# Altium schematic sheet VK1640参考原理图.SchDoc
size A4
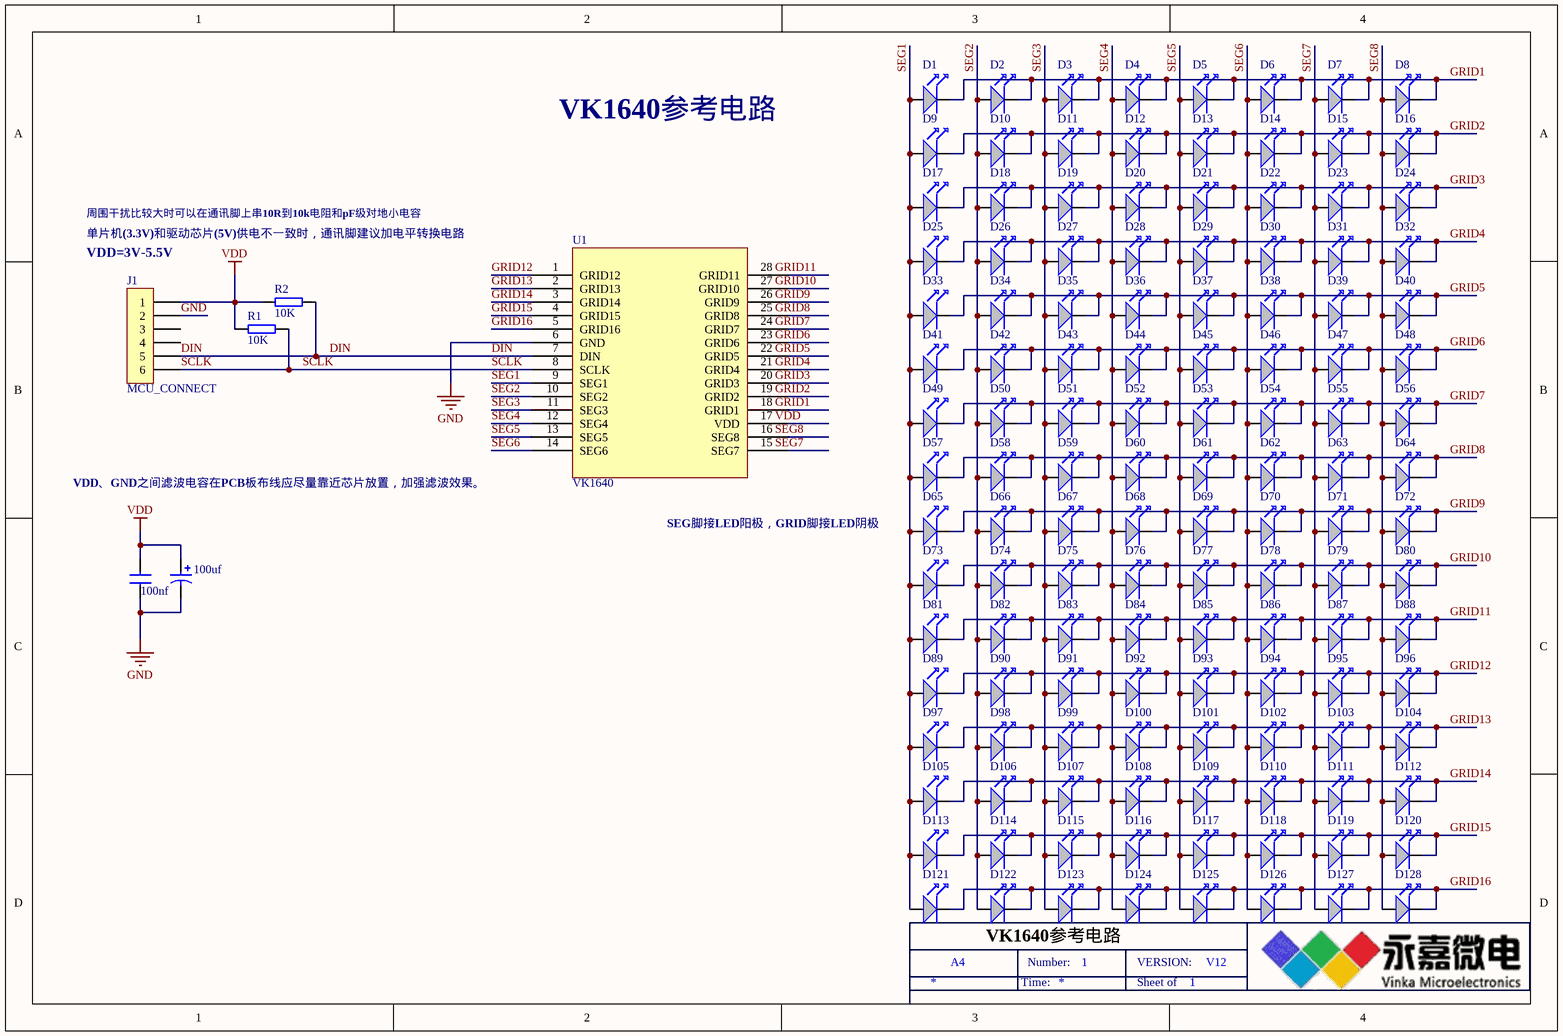
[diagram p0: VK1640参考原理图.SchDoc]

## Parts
100nf  CAP  (value not drawn)
100uf  CAP2  (value not drawn)
D1  (no value)  [1206-LED]
D2  (no value)  [1206-LED]
D3  (no value)  [1206-LED]
D4  (no value)  [1206-LED]
D5  (no value)  [1206-LED]
D6  (no value)  [1206-LED]
D7  (no value)  [1206-LED]
D8  (no value)  [1206-LED]
D9  (no value)  [1206-LED]
D10  (no value)  [1206-LED]
D11  (no value)  [1206-LED]
D12  (no value)  [1206-LED]
D13  (no value)  [1206-LED]
D14  (no value)  [1206-LED]
D15  (no value)  [1206-LED]
D16  (no value)  [1206-LED]
D17  (no value)  [1206-LED]
D18  (no value)  [1206-LED]
D19  (no value)  [1206-LED]
D20  (no value)  [1206-LED]
D21  (no value)  [1206-LED]
D22  (no value)  [1206-LED]
D23  (no value)  [1206-LED]
D24  (no value)  [1206-LED]
D25  (no value)  [1206-LED]
D26  (no value)  [1206-LED]
D27  (no value)  [1206-LED]
D28  (no value)  [1206-LED]
D29  (no value)  [1206-LED]
D30  (no value)  [1206-LED]
D31  (no value)  [1206-LED]
D32  (no value)  [1206-LED]
D33  (no value)  [1206-LED]
D34  (no value)  [1206-LED]
D35  (no value)  [1206-LED]
D36  (no value)  [1206-LED]
D37  (no value)  [1206-LED]
D38  (no value)  [1206-LED]
D39  (no value)  [1206-LED]
D40  (no value)  [1206-LED]
D41  (no value)  [1206-LED]
D42  (no value)  [1206-LED]
D43  (no value)  [1206-LED]
D44  (no value)  [1206-LED]
D45  (no value)  [1206-LED]
D46  (no value)  [1206-LED]
D47  (no value)  [1206-LED]
D48  (no value)  [1206-LED]
D49  (no value)  [1206-LED]
D50  (no value)  [1206-LED]
D51  (no value)  [1206-LED]
D52  (no value)  [1206-LED]
D53  (no value)  [1206-LED]
D54  (no value)  [1206-LED]
D55  (no value)  [1206-LED]
D56  (no value)  [1206-LED]
D57  (no value)  [1206-LED]
D58  (no value)  [1206-LED]
D59  (no value)  [1206-LED]
D60  (no value)  [1206-LED]
D61  (no value)  [1206-LED]
D62  (no value)  [1206-LED]
D63  (no value)  [1206-LED]
D64  (no value)  [1206-LED]
D65  (no value)  [1206-LED]
D66  (no value)  [1206-LED]
D67  (no value)  [1206-LED]
D68  (no value)  [1206-LED]
D69  (no value)  [1206-LED]
D70  (no value)  [1206-LED]
D71  (no value)  [1206-LED]
D72  (no value)  [1206-LED]
D73  (no value)  [1206-LED]
D74  (no value)  [1206-LED]
D75  (no value)  [1206-LED]
D76  (no value)  [1206-LED]
D77  (no value)  [1206-LED]
D78  (no value)  [1206-LED]
D79  (no value)  [1206-LED]
D80  (no value)  [1206-LED]
D81  (no value)  [1206-LED]
D82  (no value)  [1206-LED]
D83  (no value)  [1206-LED]
D84  (no value)  [1206-LED]
D85  (no value)  [1206-LED]
D86  (no value)  [1206-LED]
D87  (no value)  [1206-LED]
D88  (no value)  [1206-LED]
D89  (no value)  [1206-LED]
D90  (no value)  [1206-LED]
D91  (no value)  [1206-LED]
D92  (no value)  [1206-LED]
D93  (no value)  [1206-LED]
D94  (no value)  [1206-LED]
D95  (no value)  [1206-LED]
D96  (no value)  [1206-LED]
D97  (no value)  [1206-LED]
D98  (no value)  [1206-LED]
D99  (no value)  [1206-LED]
D100  (no value)  [1206-LED]
D101  (no value)  [1206-LED]
D102  (no value)  [1206-LED]
D103  (no value)  [1206-LED]
D104  (no value)  [1206-LED]
D105  (no value)  [1206-LED]
D106  (no value)  [1206-LED]
D107  (no value)  [1206-LED]
D108  (no value)  [1206-LED]
D109  (no value)  [1206-LED]
D110  (no value)  [1206-LED]
D111  (no value)  [1206-LED]
D112  (no value)  [1206-LED]
D113  (no value)  [1206-LED]
D114  (no value)  [1206-LED]
D115  (no value)  [1206-LED]
D116  (no value)  [1206-LED]
D117  (no value)  [1206-LED]
D118  (no value)  [1206-LED]
D119  (no value)  [1206-LED]
D120  (no value)  [1206-LED]
D121  (no value)  [1206-LED]
D122  (no value)  [1206-LED]
D123  (no value)  [1206-LED]
D124  (no value)  [1206-LED]
D125  (no value)  [1206-LED]
D126  (no value)  [1206-LED]
D127  (no value)  [1206-LED]
D128  (no value)  [1206-LED]
J1  MCU_CONNECT
R1  10K  [0603-R]
R2  10K  [0603-R]
U1  VK1640

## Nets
GND: 100nf.2 100uf.2 J1.2 U1.6(GND)
VDD: 100nf.1 100uf.1 J1.1 R1.1 R2.1
DIN: J1.5 R2.2 U1.7(DIN)
GRID1: D1.2 D2.2 D3.2 D4.2 D5.2 D6.2 D7.2 D8.2
GRID2: D9.2 D10.2 D11.2 D12.2 D13.2 D14.2 D15.2 D16.2
GRID3: D17.2 D18.2 D19.2 D20.2 D21.2 D22.2 D23.2 D24.2
GRID4: D25.2 D26.2 D27.2 D28.2 D29.2 D30.2 D31.2 D32.2
GRID5: D33.2 D34.2 D35.2 D36.2 D37.2 D38.2 D39.2 D40.2
GRID6: D41.2 D42.2 D43.2 D44.2 D45.2 D46.2 D47.2 D48.2
GRID7: D49.2 D50.2 D51.2 D52.2 D53.2 D54.2 D55.2 D56.2
GRID8: D57.2 D58.2 D59.2 D60.2 D61.2 D62.2 D63.2 D64.2
GRID9: D65.2 D66.2 D67.2 D68.2 D69.2 D70.2 D71.2 D72.2
GRID10: D73.2 D74.2 D75.2 D76.2 D77.2 D78.2 D79.2 D80.2
GRID11: D81.2 D82.2 D83.2 D84.2 D85.2 D86.2 D87.2 D88.2
GRID12: D89.2 D90.2 D91.2 D92.2 D93.2 D94.2 D95.2 D96.2 U1.1(GRID12)
GRID13: D97.2 D98.2 D99.2 D100.2 D101.2 D102.2 D103.2 D104.2 U1.2(GRID13)
GRID14: D105.2 D106.2 D107.2 D108.2 D109.2 D110.2 D111.2 D112.2 U1.3(GRID14)
GRID15: D113.2 D114.2 D115.2 D116.2 D117.2 D118.2 D119.2 D120.2 U1.4(GRID15)
GRID16: D121.2 D122.2 D123.2 D124.2 D125.2 D126.2 D127.2 D128.2 U1.5(GRID16)
SCLK: J1.6 R1.2 U1.8(SCLK)
SEG1: D1.1 D9.1 D17.1 D25.1 D33.1 D41.1 D49.1 D57.1 D65.1 D73.1 D81.1 D89.1 D97.1 D105.1 D113.1 D121.1 U1.9(SEG1)
SEG2: D2.1 D10.1 D18.1 D26.1 D34.1 D42.1 D50.1 D58.1 D66.1 D74.1 D82.1 D90.1 D98.1 D106.1 D114.1 D122.1 U1.10(SEG2)
SEG3: D3.1 D11.1 D19.1 D27.1 D35.1 D43.1 D51.1 D59.1 D67.1 D75.1 D83.1 D91.1 D99.1 D107.1 D115.1 D123.1 U1.11(SEG3)
SEG4: D4.1 D12.1 D20.1 D28.1 D36.1 D44.1 D52.1 D60.1 D68.1 D76.1 D84.1 D92.1 D100.1 D108.1 D116.1 D124.1 U1.12(SEG4)
SEG5: D5.1 D13.1 D21.1 D29.1 D37.1 D45.1 D53.1 D61.1 D69.1 D77.1 D85.1 D93.1 D101.1 D109.1 D117.1 D125.1 U1.13(SEG5)
SEG6: D6.1 D14.1 D22.1 D30.1 D38.1 D46.1 D54.1 D62.1 D70.1 D78.1 D86.1 D94.1 D102.1 D110.1 D118.1 D126.1 U1.14(SEG6)
SEG7: D7.1 D15.1 D23.1 D31.1 D39.1 D47.1 D55.1 D63.1 D71.1 D79.1 D87.1 D95.1 D103.1 D111.1 D119.1 D127.1
SEG8: D8.1 D16.1 D24.1 D32.1 D40.1 D48.1 D56.1 D64.1 D72.1 D80.1 D88.1 D96.1 D104.1 D112.1 D120.1 D128.1

Not connected (* = marked no-connect by the designer): J1 3 4; U1 15(SEG7) 16(SEG8) 17(VDD) 18(GRID1) 19(GRID2) 20(GRID3) 21(GRID4) 22(GRID5) 23(GRID6) 24(GRID7) 25(GRID8) 26(GRID9) 27(GRID10) 28(GRID11)

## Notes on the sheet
- VK1640参考电路
- 周围干扰比较大时可以在通讯脚上串10R到10k电阻和pF级对地小电容
- 单片机(3.3V)和驱动芯片(5V)供电不一致时，通讯脚建议加电平转换电路
- (near J1) VDD=3V-5.5V
- VDD、GND之间滤波电容在PCB板布线应尽量靠近芯片放置，加强滤波效果。
- SEG脚接LED阳极，GRID脚接LED阴极
- A4
- Time:
- Number:
- 1
- Sheet of
- VERSION:
- V12
- Labels drawn without touching a wire or pin: GRID1, GRID2, GRID3, GRID4, GRID5, GRID6, GRID7, GRID8, GRID9, GRID10, GRID11, SEG7, SEG8, VDD

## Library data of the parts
100nf = CAP: Capacitor
100uf = CAP2: Bi-Polar Capacitor
D1-D128 = LED: Text Field1: 30; Text Field2: 20
J1 = CON6: Connector
R1 R2 = RES: Resistor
